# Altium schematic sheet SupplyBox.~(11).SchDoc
size B; SheetNumber: 1; SheetTotal: 1
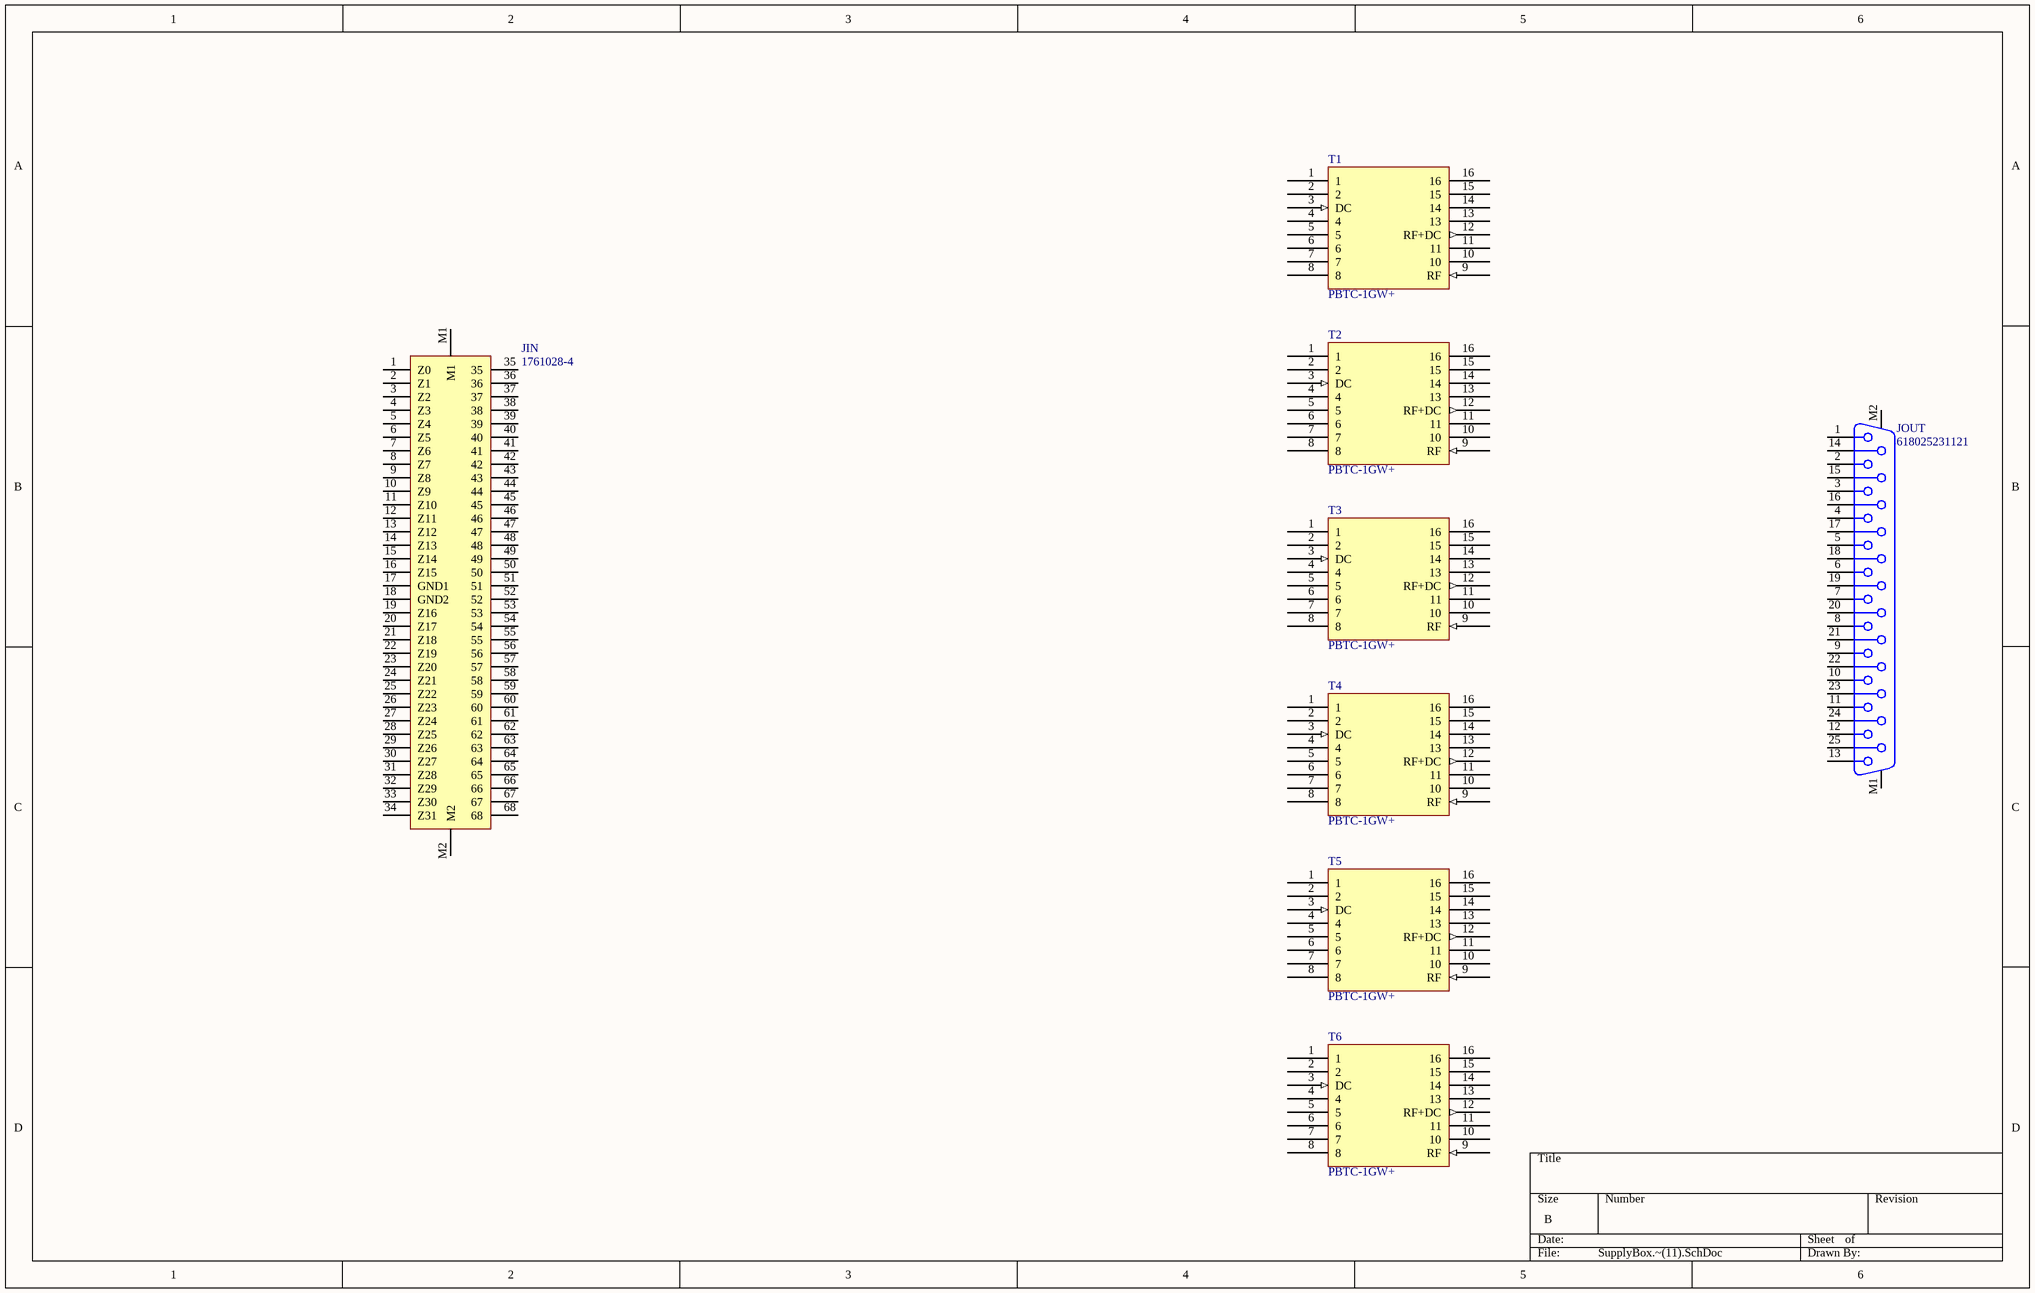
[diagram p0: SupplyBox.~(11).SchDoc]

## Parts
JIN  1761028-4  [1761028-4-Footprint-1]
JOUT  618025231121  [618025231121]
T1  PBTC-1GW+  [PBTC-1GW+]
T2  PBTC-1GW+  [PBTC-1GW+]
T3  PBTC-1GW+  [PBTC-1GW+]
T4  PBTC-1GW+  [PBTC-1GW+]
T5  PBTC-1GW+  [PBTC-1GW+]
T6  PBTC-1GW+  [PBTC-1GW+]

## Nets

Not connected (* = marked no-connect by the designer): JIN 1(Z0) 2(Z1) 3(Z2) 4(Z3) 5(Z4) 6(Z5) 7(Z6) 8(Z7) 9(Z8) 10(Z9) 11(Z10) 12(Z11) 13(Z12) 14(Z13) 15(Z14) 16(Z15) 17(GND1) 18(GND2) 19(Z16) 20(Z17) 21(Z18) 22(Z19) 23(Z20) 24(Z21) 25(Z22) 26(Z23) 27(Z24) 28(Z25) 29(Z26) 30(Z27) 31(Z28) 32(Z29) 33(Z30) 34(Z31) 35 36 37 38 39 40 41 42 43 44 45 46 47 48 49 50 51 52 53 54 55 56 57 58 59 60 61 62 63 64 65 66 67 68 M1 M2; JOUT 1 2 3 4 5 6 7 8 9 10 11 12 13 14 15 16 17 18 19 20 21 22 23 24 25 M1 M2; T1 1 2 3(DC) 4 5 6 7 8 9(RF) 10 11 12(RF+DC) 13 14 15 16; T2 1 2 3(DC) 4 5 6 7 8 9(RF) 10 11 12(RF+DC) 13 14 15 16; T3 1 2 3(DC) 4 5 6 7 8 9(RF) 10 11 12(RF+DC) 13 14 15 16; T4 1 2 3(DC) 4 5 6 7 8 9(RF) 10 11 12(RF+DC) 13 14 15 16; T5 1 2 3(DC) 4 5 6 7 8 9(RF) 10 11 12(RF+DC) 13 14 15 16; T6 1 2 3(DC) 4 5 6 7 8 9(RF) 10 11 12(RF+DC) 13 14 15 16

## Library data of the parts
JIN = CMP-002-00071-1: Telecom and Datacom Connector, 68 Contact(s), Female, Right Angle, Solder Terminal, #2-56, Receptacle
JOUT = CMP-1502-00202-2: NexarPartId: 18818207; Pitch: 2.77mm; Operating Supply Voltage: 125V; Gender: Female; Insulation Resistance: 5GΩ; Contact Resistance: 30mΩ; Current Rating: 3A; Number of Contacts: 25
T1-T6 = CMP-00025-00003-1: Monitor TEE DC Block, 0.1MHz Min, 1000MHz Max, 1dB Insertion Loss-Max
